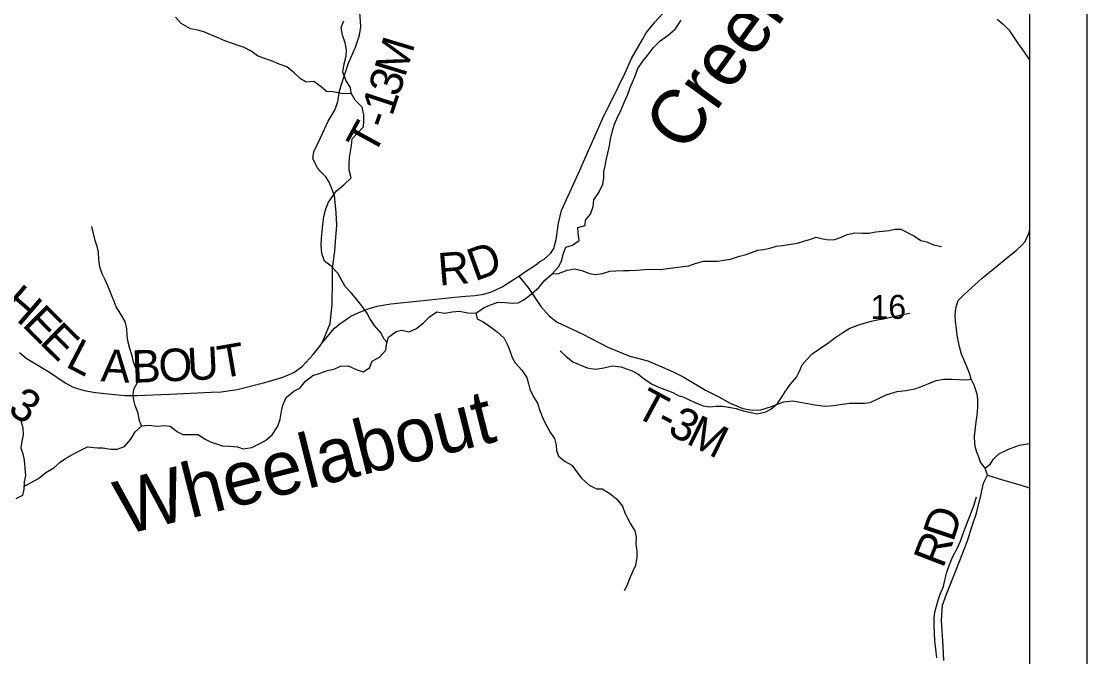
# Model space of a CAD drawing. Extents: x 0 to 34, y 0 to 22.
# Drawn here: x 28.554 to 30.417, y 15.55 to 16.661 of the extents above; entities that cross this region are included whole.
import ezdxf

# ---------------------------------------------------------------- set-up
doc = ezdxf.new("R2010")
doc.units = 0
for name, color, linetype in [('GM_X_County_Road', 7, 'Continuous'), ('GM_X_County_Road_Text', 7, 'Continuous'), ('GM_X_Minor_River', 7, 'Continuous'), ('GM_X_Minor_River_Text', 7, 'Continuous'), ('GM_X_Section_Text', 7, 'Continuous'), ('GM_X_Township_Road', 7, 'Continuous'), ('GM_X_Township_Road_Text', 7, 'Continuous'), ('SH_Data', 7, 'Continuous')]:
    doc.layers.add(name, color=color, linetype=linetype)

msp = doc.modelspace()

# ---------------------------------------------------------------- linework, layer by layer
at = {"layer": 'GM_X_County_Road'}
for points in [[(28.5504, 16.0823), (28.5624, 16.0722), (28.6033, 16.0475), (28.6306, 16.0293), (28.6446, 16.0217), (28.6634, 16.0157), (28.6832, 16.0124), (28.7339, 16.0071), (28.7558, 16.0069), (28.8133, 16.0092), (28.8859, 16.0129), (28.903, 16.0134), (28.9311, 16.0176), (28.9798, 16.0295), (29.0076, 16.0379), (29.017, 16.0412), (29.0305, 16.0472), (29.0451, 16.0574), (29.0641, 16.0787), (29.0737, 16.0909), (29.0797, 16.099), (29.1011, 16.1248), (29.1115, 16.1328), (29.1198, 16.1388), (29.1299, 16.1458), (29.1427, 16.1516), (29.1583, 16.1581), (29.1757, 16.1633), (29.1997, 16.1674), (29.2676, 16.1742), (29.3116, 16.1789), (29.3303, 16.1805), (29.3472, 16.1818), (29.3621, 16.1844), (29.3761, 16.1885), (29.3948, 16.1971), (29.4235, 16.2157), (29.4372, 16.2247), (29.4483, 16.2321), (29.4555, 16.2371), (29.4605, 16.241), (29.4679, 16.2453), (29.4735, 16.2499), (29.4792, 16.2553), (29.485, 16.264), (29.4889, 16.2797), (29.4928, 16.3083), (29.4984, 16.3303), (29.5283, 16.396), (29.5724, 16.496), (29.586, 16.5224), (29.6097, 16.5709), (29.6205, 16.5965), (29.6398, 16.6297), (29.6461, 16.6414), (29.6615, 16.6599), (29.6887, 16.6896)], [(30.2434, 15.8675), (30.239, 15.8799), (30.2311, 15.8903), (30.2282, 15.8989), (30.2244, 15.9078), (30.2222, 15.9157), (30.2213, 15.9233), (30.2206, 15.9353), (30.2216, 15.9451), (30.2228, 15.9565), (30.2251, 15.9723), (30.2263, 15.9866), (30.2263, 16.0005), (30.2251, 16.0094), (30.22, 16.0249), (30.2144, 16.0358), (30.2124, 16.0445), (30.2091, 16.0531), (30.2035, 16.0659), (30.1976, 16.0795), (30.1941, 16.092), (30.1906, 16.1089), (30.1889, 16.1225), (30.1871, 16.1373), (30.1866, 16.1476), (30.1879, 16.1595), (30.1922, 16.1733), (30.2019, 16.1832), (30.2338, 16.2124), (30.2786, 16.2488), (30.2941, 16.261), (30.3027, 16.269), (30.3091, 16.2761), (30.315, 16.2889), (30.3167, 16.295)], [(30.1668, 15.5437), (30.1656, 15.5687), (30.1627, 15.6137), (30.1643, 15.6403), (30.1713, 15.6596), (30.1884, 15.702), (30.2083, 15.7527), (30.216, 15.7771), (30.2238, 15.8014), (30.2314, 15.8321), (30.2365, 15.8536), (30.2434, 15.8675)], [(30.2434, 15.8675), (30.2697, 15.8593), (30.2839, 15.8552), (30.3039, 15.8495), (30.3167, 15.8456)]]:
    msp.add_lwpolyline(points, dxfattribs=at)
at = {"layer": 'GM_X_Minor_River'}
for points in [[(29.1312, 16.5345), (29.1135, 16.5349), (29.0991, 16.538), (29.0873, 16.5387), (29.0779, 16.5467), (29.065, 16.5558), (29.0521, 16.5546), (29.0419, 16.5607), (29.0309, 16.5709), (29.018, 16.5816), (29.0047, 16.5861), (28.9911, 16.5922), (28.9775, 16.5971), (28.9669, 16.6009), (28.9559, 16.6088), (28.9437, 16.6157), (28.9331, 16.6187), (28.921, 16.6232), (28.9096, 16.627), (28.8994, 16.632), (28.885, 16.6376), (28.8729, 16.6429), (28.8623, 16.6456), (28.8494, 16.6479), (28.8335, 16.6577), (28.8236, 16.6687)], [(29.1932, 16.0996), (29.1874, 16.1063), (29.1829, 16.1162), (29.1711, 16.1295), (29.1631, 16.1416), (29.1578, 16.1515), (29.1491, 16.1636), (29.1404, 16.1746), (29.1313, 16.186), (29.1199, 16.1977), (29.1142, 16.208), (29.1074, 16.2208), (29.0953, 16.233), (29.0839, 16.2421), (29.079, 16.2554), (29.0782, 16.2698), (29.0789, 16.2823), (29.0797, 16.294), (29.0808, 16.3062), (29.0827, 16.3198), (29.0864, 16.3331), (29.091, 16.3449), (29.0978, 16.3551), (29.1046, 16.3646), (29.1178, 16.3752), (29.1307, 16.3874), (29.1273, 16.401), (29.1269, 16.4124), (29.1276, 16.423), (29.1291, 16.4337), (29.131, 16.4439), (29.1325, 16.4557), (29.1408, 16.4652), (29.1522, 16.4769), (29.1529, 16.4864), (29.1525, 16.4978), (29.1495, 16.5111), (29.1373, 16.5236), (29.1305, 16.5357), (29.1294, 16.5456), (29.1218, 16.557), (29.1157, 16.5725), (29.118, 16.5869), (29.1217, 16.6006), (29.1221, 16.6116), (29.1202, 16.6237), (29.1156, 16.637), (29.1133, 16.6503), (29.1175, 16.6624)], [(29.6137, 16.5321), (29.6182, 16.5454), (29.6265, 16.5644), (29.6318, 16.5788), (29.6405, 16.5917), (29.6488, 16.6016), (29.6594, 16.6156), (29.6707, 16.627), (29.6847, 16.6369), (29.6976, 16.6483), (29.7078, 16.6634)], [(30.2599, 16.6648), (30.2709, 16.6561), (30.2804, 16.6463), (30.2887, 16.6341), (30.2959, 16.6235), (30.3035, 16.6133), (30.3096, 16.6038), (30.3164, 16.5939), (30.3167, 16.5935)], [(28.6696, 15.9172), (28.6867, 15.9153), (28.6965, 15.9153), (28.7102, 15.913), (28.7211, 15.913), (28.734, 15.918), (28.7454, 15.9305), (28.7529, 15.9434), (28.7646, 15.954), (28.7771, 15.9552), (28.7908, 15.9533), (28.804, 15.9548), (28.8139, 15.9533), (28.8267, 15.9434), (28.8362, 15.9389), (28.8499, 15.9385), (28.8631, 15.9385), (28.8741, 15.9313), (28.8858, 15.9256), (28.8953, 15.9226), (28.9048, 15.9192), (28.9177, 15.9184), (28.9317, 15.9173), (28.9415, 15.9139), (28.9567, 15.9162), (28.9707, 15.923), (28.9805, 15.9283), (28.9926, 15.9382), (29.0024, 15.9534), (29.0066, 15.9655), (29.0085, 15.9795), (29.0111, 15.9902), (29.0168, 16.0034), (29.03, 16.0148), (29.0406, 16.0198), (29.0508, 16.0323), (29.0633, 16.0418), (29.0762, 16.0463), (29.0894, 16.0509), (29.1019, 16.0536), (29.1117, 16.0585), (29.1254, 16.0589), (29.1394, 16.0524), (29.1515, 16.0483), (29.1625, 16.0551), (29.167, 16.0669), (29.1799, 16.0741), (29.1909, 16.0862), (29.1924, 16.0965), (29.1958, 16.109), (29.209, 16.1189), (29.2188, 16.1211), (29.2321, 16.1185), (29.245, 16.1242), (29.2578, 16.1348), (29.2673, 16.1447), (29.2805, 16.153), (29.2938, 16.1511), (29.307, 16.153), (29.3199, 16.1546), (29.3347, 16.1515), (29.3487, 16.1512), (29.3631, 16.1607), (29.3729, 16.1652), (29.3869, 16.1702), (29.3998, 16.1694), (29.4123, 16.1683), (29.4225, 16.169), (29.4327, 16.1743), (29.4452, 16.1842), (29.4584, 16.1956), (29.4694, 16.2085), (29.4819, 16.2199), (29.4936, 16.2324), (29.4985, 16.2423), (29.5019, 16.2556), (29.5057, 16.2662), (29.5178, 16.2696), (29.5292, 16.2783), (29.5272, 16.2912), (29.5269, 16.3007), (29.5397, 16.3041), (29.5401, 16.3136), (29.5488, 16.3242), (29.5537, 16.3375), (29.5548, 16.3493), (29.5635, 16.3622), (29.5703, 16.3766), (29.5722, 16.3865), (29.5726, 16.3982), (29.5744, 16.4081), (29.5767, 16.4187), (29.5793, 16.4308), (29.5824, 16.4437), (29.5842, 16.4551), (29.5876, 16.4695), (29.591, 16.4813), (29.5948, 16.4908), (29.602, 16.5052), (29.608, 16.5192), (29.6137, 16.5321)], [(28.7638, 15.9532), (28.7601, 15.965), (28.7582, 15.976), (28.7529, 15.9893), (28.7506, 15.9988), (28.7491, 16.0086), (28.7506, 16.0181), (28.757, 16.0299), (28.7581, 16.0428), (28.7551, 16.0526), (28.7505, 16.0633), (28.7482, 16.0739), (28.7437, 16.0894), (28.7402, 16.1023), (28.7387, 16.1122), (28.7383, 16.1236), (28.7353, 16.1365), (28.7277, 16.1494), (28.7197, 16.1619), (28.7163, 16.1714), (28.7106, 16.1842), (28.7053, 16.1987), (28.7011, 16.2081), (28.6954, 16.2199), (28.6912, 16.2317), (28.6893, 16.2446), (28.6886, 16.2574), (28.6863, 16.2677), (28.6829, 16.2779), (28.6802, 16.2904), (28.6768, 16.3026)], [(29.4819, 16.2199), (29.4932, 16.2203), (29.5084, 16.2263), (29.5213, 16.2286), (29.5341, 16.2256), (29.547, 16.2203), (29.5572, 16.2188), (29.5701, 16.2203), (29.5826, 16.2241), (29.5932, 16.2249), (29.6065, 16.2256), (29.6174, 16.2253), (29.6303, 16.226), (29.6436, 16.2272), (29.6576, 16.2276), (29.6712, 16.2272), (29.6837, 16.2291), (29.6977, 16.2306), (29.711, 16.2325), (29.7208, 16.234), (29.7318, 16.2378), (29.7469, 16.242), (29.7719, 16.242), (29.7829, 16.2435), (29.7939, 16.2454), (29.8098, 16.2504), (29.8211, 16.2538), (29.8321, 16.2576), (29.8419, 16.261), (29.8518, 16.2625), (29.8624, 16.2648), (29.8741, 16.2679), (29.8843, 16.269), (29.9108, 16.2736), (29.9222, 16.2766), (29.932, 16.2797), (29.9438, 16.2838), (29.9551, 16.2812), (29.9654, 16.2793), (29.976, 16.2797), (29.9862, 16.2835), (29.9979, 16.2884), (30.0112, 16.2915), (30.0244, 16.2911), (30.0358, 16.2907), (30.0479, 16.293), (30.0596, 16.2945), (30.071, 16.2957), (30.0812, 16.2976), (30.0914, 16.2976), (30.1157, 16.2854), (30.1267, 16.2782), (30.1369, 16.2756), (30.149, 16.2707), (30.1627, 16.2676)], [(29.3487, 16.1512), (29.351, 16.1409), (29.3612, 16.1356), (29.3741, 16.1269), (29.3858, 16.1182), (29.398, 16.1072), (29.4044, 16.0943), (29.4078, 16.0848), (29.412, 16.0734), (29.4173, 16.0639), (29.4291, 16.0511), (29.4378, 16.0382), (29.4408, 16.0275), (29.4431, 16.0181), (29.4492, 16.0044), (29.4564, 15.9934), (29.4606, 15.9805), (29.4667, 15.9642), (29.472, 15.9547), (29.4788, 15.9418), (29.486, 15.9316), (29.489, 15.9202), (29.4898, 15.9107), (29.4932, 15.9009), (29.505, 15.8918), (29.5164, 15.8849), (29.5255, 15.8721), (29.533, 15.8622), (29.5467, 15.8504), (29.5596, 15.844), (29.5694, 15.844), (29.5827, 15.8357), (29.5944, 15.8262), (29.6047, 15.8137), (29.6088, 15.8019), (29.6138, 15.7924), (29.6191, 15.7826), (29.6263, 15.7701), (29.6286, 15.7594), (29.6282, 15.7484), (29.6301, 15.7344), (29.6298, 15.7242), (29.6275, 15.7097), (29.6222, 15.6987), (29.6169, 15.6851), (29.6131, 15.6756), (29.6079, 15.6654)], [(29.4961, 16.0848), (29.5059, 16.0757), (29.5184, 16.0659), (29.5434, 16.0553), (29.5578, 16.053), (29.5726, 16.0553), (29.5873, 16.0591), (29.6025, 16.0572), (29.612, 16.0534), (29.6218, 16.0504), (29.632, 16.0447), (29.6427, 16.0364), (29.6559, 16.0273), (29.6696, 16.0212), (29.693, 16.0121), (29.7025, 16.0072), (29.7124, 16.0038), (29.7218, 15.9996), (29.7332, 15.9943), (29.7461, 15.989), (29.7571, 15.9871), (29.7688, 15.9882), (29.7798, 15.9883), (29.7904, 15.9867), (29.8036, 15.9845), (29.8161, 15.9803), (29.8302, 15.9773), (29.84, 15.975), (29.8544, 15.9777), (29.8646, 15.983), (29.8763, 15.9928), (29.8839, 16.005), (29.8899, 16.0145), (29.8986, 16.0266), (29.9092, 16.0391), (29.9145, 16.0494), (29.9194, 16.0608), (29.9277, 16.0703), (29.9364, 16.0797), (29.9512, 16.0896), (29.9656, 16.0999), (29.9765, 16.1078), (29.9902, 16.1169), (30.0023, 16.1249), (30.0167, 16.1302), (30.0291, 16.134), (30.0405, 16.1371), (30.0503, 16.139), (30.0613, 16.1413), (30.0712, 16.1435), (30.0825, 16.1458), (30.0946, 16.1485), (30.1075, 16.1508)], [(28.5522, 15.9655), (28.5564, 15.9507), (28.5572, 15.9378), (28.5546, 15.9272), (28.5531, 15.9154), (28.5562, 15.9048), (28.5585, 15.8938), (28.5601, 15.8798), (28.5612, 15.8669), (28.5586, 15.8559), (28.5579, 15.843), (28.5557, 15.832), (28.544, 15.8263)], [(28.5582, 15.8477), (28.5696, 15.854), (28.5836, 15.862), (28.5968, 15.8723), (28.6108, 15.8803), (28.6214, 15.8902), (28.6312, 15.8966), (28.6459, 15.9054), (28.6696, 15.9172)], [(30.1548, 15.548), (30.1532, 15.559), (30.151, 15.578), (30.1506, 15.5913), (30.1502, 15.6038), (30.1502, 15.6174), (30.1509, 15.6284), (30.1539, 15.6387), (30.1569, 15.6493), (30.1603, 15.6595), (30.1664, 15.6732), (30.1686, 15.6842), (30.1724, 15.6979), (30.1766, 15.7115), (30.1826, 15.7252), (30.1902, 15.7392), (30.1962, 15.7521), (30.2007, 15.7654), (30.206, 15.7794), (30.2109, 15.7931), (30.2166, 15.8064), (30.22, 15.8159), (30.2237, 15.8295)]]:
    msp.add_lwpolyline(points, dxfattribs=at)
at = {"layer": 'GM_X_Township_Road'}
for points in [[(29.1045, 16.3269), (29.1044, 16.3277), (29.1013, 16.3561), (29.0959, 16.3699), (29.0917, 16.3811), (29.0862, 16.3892), (29.0774, 16.3983), (29.0719, 16.4048), (29.0636, 16.4209), (29.0651, 16.4331), (29.0771, 16.4576), (29.0903, 16.4866), (29.1024, 16.5068), (29.107, 16.5208), (29.1099, 16.5398), (29.118, 16.5652), (29.126, 16.5881), (29.1383, 16.6163), (29.145, 16.6369), (29.1474, 16.652), (29.145, 16.6853)], [(29.0797, 16.099), (29.094, 16.1326), (29.0974, 16.1667), (29.0979, 16.208), (29.0979, 16.2294), (29.1021, 16.2593), (29.1031, 16.2765), (29.1055, 16.3046), (29.1045, 16.3269)], [(29.4235, 16.2157), (29.4414, 16.1941), (29.4621, 16.1628), (29.4774, 16.1457), (29.4907, 16.1352), (29.5068, 16.1274), (29.5354, 16.114), (29.5805, 16.0908), (29.6179, 16.0758), (29.649, 16.0675), (29.6695, 16.0589), (29.6934, 16.0484), (29.7123, 16.0391), (29.75, 16.0165), (29.7737, 16.0046), (29.793, 15.9933), (29.8156, 15.9844), (29.8315, 15.9815), (29.8471, 15.9817), (29.8656, 15.9879), (29.8873, 15.9959), (29.9031, 15.9978), (29.9159, 15.9951), (29.9412, 15.9906), (29.9591, 15.9885), (29.9733, 15.9894), (30.0019, 15.9937), (30.0274, 15.9933), (30.0381, 15.9947), (30.0659, 16.0079), (30.0852, 16.0142), (30.1006, 16.0157), (30.1159, 16.0186), (30.1262, 16.0221), (30.1404, 16.028), (30.1533, 16.033), (30.1667, 16.0354), (30.1807, 16.0354), (30.207, 16.0346), (30.2144, 16.0358)], [(30.239, 15.8799), (30.2483, 15.8872), (30.2532, 15.8951), (30.263, 15.9049), (30.2798, 15.9131), (30.2991, 15.9201), (30.3167, 15.9229)]]:
    msp.add_lwpolyline(points, dxfattribs=at)
at = {"layer": 'SH_Data'}
for points in [[(23.4167, 21), (30.4167, 21), (30.4167, 14), (23.4167, 14)], [(23.5167, 20.9), (30.3167, 20.9), (30.3167, 14.1), (23.5167, 14.1)]]:
    msp.add_lwpolyline(points, close=True, dxfattribs=at)

# ---------------------------------------------------------------- texts
at = {"layer": 'GM_X_County_Road_Text'}
for s, rotation, p in [('D', 19.8619, (29.3467, 16.2063)), ('R', 4.7474, (29.2845, 16.199)), ('H', 319.1869, (28.5165, 16.1618)), ('E', 314.7515, (28.5535, 16.1299)), ('E', 315.4597, (28.584, 16.0991)), ('L', 332.472, (28.6291, 16.0585)), ('T', 9.8547, (28.9026, 16.0366)), ('A', 356.7987, (28.692, 16.032)), ('B', 2.163, (28.7478, 16.0291)), ('O', 2.6005, (28.7949, 16.0309)), ('U', 2.93, (28.8452, 16.0332)), ('3', 327.2842, (28.5279, 15.9776)), ('D', 71.5078, (30.183, 15.7494)), ('R', 68.9204, (30.1653, 15.7033))]:
    msp.add_text(s, height=0.0568, rotation=rotation, dxfattribs=at).set_placement(p)
at = {"layer": 'GM_X_Minor_River_Text'}
for s, height, rotation, p in [('Creek', 0.0947, 53.9563, (29.7139, 16.4281)), ('Wheelabout', 0.09469, 14.1084, (28.7326, 15.7626))]:
    msp.add_text(s, height=height, rotation=rotation, dxfattribs=at).set_placement(p)
at = {"layer": 'GM_X_Section_Text'}
msp.add_text('16', height=0.04186, rotation=0, dxfattribs=at).set_placement((30.0386, 16.141))
at = {"layer": 'GM_X_Township_Road_Text'}
for s, rotation, p in [('M', 73.1232, (29.2245, 16.5618)), ('3', 71.9011, (29.2132, 16.5273)), ('1', 71.6906, (29.2022, 16.4939)), ('T', 61.3704, (29.1697, 16.4243)), ('-', 70.7865, (29.1942, 16.4709)), ('T', 331.7442, (29.6235, 15.9724)), ('3', 331.9286, (29.6817, 15.9411)), ('-', 331.7906, (29.661, 15.9522)), ('M', 333.6327, (29.7142, 15.9238))]:
    msp.add_text(s, height=0.0568, rotation=rotation, dxfattribs=at).set_placement(p)

doc.saveas('drawing.dxf')
